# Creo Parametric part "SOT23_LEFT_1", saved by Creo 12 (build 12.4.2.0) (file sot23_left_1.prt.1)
Units: Custom; MM, KILOGRAM, SECS

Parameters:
  PTC_WM_ITERATION = "0"
  PTC_WM_VERSION = "-.0"
  PTC_WM_LIFECYCLE_STATE = "In Work"
  PTC_WM_LIFECYCLE = "MO_CADDocument"
  PTC_WM_CREATED_BY = "Maximilian Roepper (Z0017RMS: MO)"
  PTC_WM_CREATED_ON = "18-Sep-26 11:36:42 AM"
  PTC_WM_MODIFIED_BY = "Maximilian Roepper (Z0017RMS: MO)"
  PTC_WM_MODIFIED_ON = "18-Sep-26 11:36:46 AM"
  PDMLINKNUMBER = "PDM000071455139"
  PTC_WM_NAME = "sot23_left_1.prt"
  PTC_WM_NUMBER = "PDM000071455139"

Other parameters: WEIGHT, WEIGHT_FACTOR, WEIGHT_ADD, _MASS_TEMP, _DIFF_TEMP, MC_ERRORS, SUPPLIER

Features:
  1. coordinate system
  2. datum plane "PRT_YZ"
  3. datum plane "PRT_XY"
  4. datum plane "PRT_XZ"
  5. coordinate system
  6. datum axis
  7. datum axis
  8. datum axis
  9. coordinate system
  10. imported feature

Other named items: PRT, SIEMENS_MO, DRW_VIEW_ORG, PRT_X, PRT_Y, PRT_Z, CS0, ROUGH_GROB

Layers: 00_STD_CSYS-KSYS, 01_STD_PLANES-EBENEN, 02_STD_AXES-ACHSEN, 03_STD_CSYS-KSYS, 24_IMPORT_FEAT-IMPORT_KE

Surfaces: 8 plane, 2 cylinder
